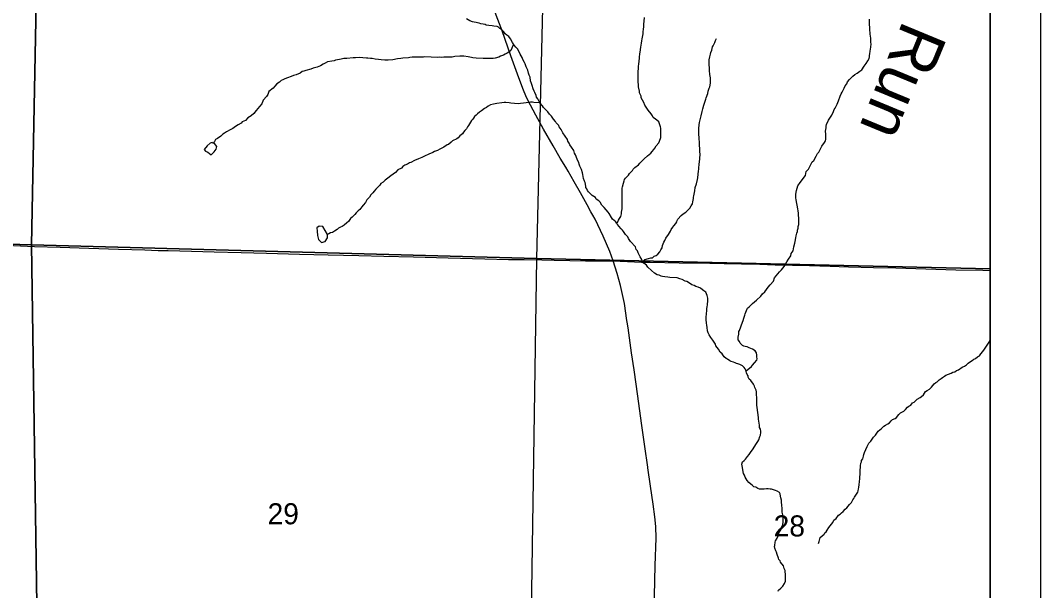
# Model space of a CAD drawing. Extents: x 0 to 34, y 0 to 22.
# Drawn here: x 6.971 to 9, y 18.998 to 20.132 of the extents above; entities that cross this region are included whole.
import ezdxf

# ---------------------------------------------------------------- set-up
doc = ezdxf.new("R2010")
doc.units = 0
for name, color, linetype in [('Default', 7, 'Continuous'), ('GM_X_Minor_River', 7, 'Continuous'), ('GM_X_Minor_River_Text', 7, 'Continuous'), ('GM_X_Section', 7, 'Continuous'), ('GM_X_Section_Text', 7, 'Continuous'), ('GM_X_State_Route', 7, 'Continuous'), ('SH_Data', 7, 'Continuous')]:
    doc.layers.add(name, color=color, linetype=linetype)

msp = doc.modelspace()

# ---------------------------------------------------------------- linework, layer by layer
at = {"layer": 'Default'}
for points in [[(8.9, 17.6104), (8.9, 20.9), (6.0871, 20.9), (6.0839, 20.7194), (6.0809, 20.5156), (6.08, 20.4768), (6.0777, 20.3704), (6.0696, 20.0002), (6.0632, 19.7108), (6.0568, 19.5343), (5.9893, 17.6676), (6.9889, 17.643), (7.0308, 17.6406), (8.0065, 17.6245)], [(8.9, 19.6382), (8.9, 20.6903), (8.0224, 20.7109), (7.9969, 19.6588)], [(8.9, 18.6218), (8.9, 19.6382), (7.9969, 19.6588), (7.9821, 18.6451)]]:
    msp.add_lwpolyline(points, close=True, dxfattribs=at)
at = {"layer": 'GM_X_Minor_River'}
for points in [[(7.9702, 20.0545), (7.9685, 20.0587), (7.9649, 20.0653), (7.9603, 20.0754), (7.9562, 20.0793), (7.9529, 20.0833), (7.9496, 20.0883), (7.9453, 20.0957), (7.9424, 20.1004), (7.9383, 20.1028), (7.9346, 20.106), (7.932, 20.1095), (7.928, 20.1135), (7.9242, 20.1163), (7.9213, 20.119), (7.9187, 20.1203), (7.9126, 20.1212), (7.9088, 20.1214), (7.9023, 20.122), (7.8974, 20.1233), (7.8948, 20.1241), (7.891, 20.125), (7.8868, 20.1259), (7.8834, 20.1268), (7.8796, 20.1277), (7.877, 20.1282), (7.8732, 20.1291), (7.8698, 20.1299), (7.8645, 20.1317), (7.8577, 20.1353)], [(8.1566, 19.7284), (8.1581, 19.7303), (8.1606, 19.7348), (8.1622, 19.7381), (8.1647, 19.7426), (8.1664, 19.7479), (8.1665, 19.7509), (8.1674, 19.7574), (8.1678, 19.7684), (8.1676, 19.7749), (8.1674, 19.778), (8.1675, 19.7821), (8.1673, 19.7871), (8.1677, 19.7989), (8.1681, 19.8015), (8.1703, 19.8087), (8.1716, 19.8132), (8.1724, 19.8159), (8.1744, 19.8185), (8.18, 19.8244), (8.1824, 19.8281), (8.1883, 19.8336), (8.1895, 19.8362), (8.1931, 19.8399), (8.2001, 19.8454), (8.2029, 19.8487), (8.208, 19.8535), (8.2116, 19.8572), (8.2183, 19.8631), (8.2246, 19.8686), (8.227, 19.8719), (8.2309, 19.8756), (8.2329, 19.8786), (8.2353, 19.8831), (8.2405, 19.8886), (8.2421, 19.8923), (8.2443, 19.8995), (8.2444, 19.9022), (8.2448, 19.9052), (8.2448, 19.9147), (8.2445, 19.9182), (8.2442, 19.9208), (8.2421, 19.927), (8.2404, 19.9305), (8.2363, 19.9337), (8.2337, 19.9361), (8.2296, 19.9393), (8.2278, 19.9424), (8.2252, 19.9463), (8.2194, 19.9541), (8.2169, 19.958), (8.2125, 19.9638), (8.2104, 19.9689), (8.2057, 19.9786), (8.2051, 19.9816), (8.2022, 19.9882), (8.202, 19.9916), (8.2003, 20.0005), (8.1998, 20.0054), (8.1995, 20.0089), (8.1994, 20.0165), (8.1996, 20.0249), (8.1994, 20.0291), (8.2001, 20.0386), (8.2002, 20.042), (8.2007, 20.045), (8.2013, 20.0519), (8.2018, 20.0564), (8.2019, 20.0591), (8.2029, 20.0659), (8.2034, 20.0693), (8.2045, 20.0792), (8.2063, 20.0875), (8.2068, 20.0921), (8.2077, 20.0958), (8.2082, 20.0989), (8.2092, 20.1057), (8.2094, 20.1103), (8.2099, 20.1144), (8.2105, 20.1205), (8.211, 20.1247), (8.2116, 20.1311), (8.2118, 20.1384)], [(8.5845, 19.9442), (8.5878, 19.9513), (8.5894, 19.9551), (8.5914, 19.9577), (8.5927, 19.9607), (8.5955, 19.9655), (8.5967, 19.9689), (8.598, 19.9727), (8.601, 19.9817), (8.6031, 19.9866), (8.6054, 19.9896), (8.6091, 19.9974), (8.6112, 20.0023), (8.6144, 20.0064), (8.6157, 20.0102), (8.62, 20.0146), (8.6267, 20.0212), (8.6307, 20.0249), (8.6353, 20.0274), (8.6404, 20.0318), (8.6443, 20.0343), (8.6491, 20.0414), (8.6507, 20.044), (8.6527, 20.0466), (8.6563, 20.0518), (8.6592, 20.057), (8.6597, 20.0601), (8.6598, 20.0627), (8.6602, 20.0658), (8.6608, 20.0715), (8.6626, 20.079), (8.6628, 20.0859), (8.6625, 20.0886), (8.6624, 20.0969), (8.6612, 20.1054), (8.6609, 20.1092), (8.6606, 20.1119), (8.6601, 20.1199), (8.6599, 20.1233), (8.6598, 20.1321), (8.6595, 20.1351)], [(8.2082, 19.6528), (8.2125, 19.6571), (8.2198, 19.6588), (8.2248, 19.6598), (8.2279, 19.6604), (8.231, 19.6634), (8.2353, 19.6647), (8.2384, 19.6673), (8.2424, 19.6717), (8.2448, 19.6758), (8.2469, 19.6803), (8.2478, 19.6849), (8.249, 19.6879), (8.2503, 19.6913), (8.2527, 19.6946), (8.2547, 19.6991), (8.2599, 19.7062), (8.2616, 19.7099), (8.2636, 19.7133), (8.2649, 19.7163), (8.2681, 19.7211), (8.2701, 19.7237), (8.2744, 19.7285), (8.2764, 19.7315), (8.2773, 19.7342), (8.2781, 19.7372), (8.2853, 19.7446), (8.2888, 19.7479), (8.2942, 19.7511), (8.297, 19.7537), (8.3021, 19.7588), (8.3046, 19.7633), (8.3074, 19.7678), (8.3079, 19.7716), (8.3093, 19.778), (8.3097, 19.7807), (8.3102, 19.7837), (8.3121, 19.7932), (8.313, 19.8), (8.3152, 19.8075), (8.3174, 19.8158), (8.3179, 19.8193), (8.3195, 19.8329), (8.32, 19.8356), (8.32, 19.8382), (8.3211, 19.8462), (8.3212, 19.8511), (8.3222, 19.8568), (8.3225, 19.8667), (8.3222, 19.8702), (8.3224, 19.8747), (8.3213, 19.8862), (8.3213, 19.8889), (8.3205, 19.8984), (8.32, 19.9068), (8.3202, 19.9106), (8.3199, 19.9137), (8.32, 19.9171), (8.3206, 19.9247), (8.3216, 19.9292), (8.3233, 19.9372), (8.3242, 19.9398), (8.3247, 19.9428), (8.3269, 19.9511), (8.3273, 19.9538), (8.3282, 19.9568), (8.3303, 19.9636), (8.3312, 19.9678), (8.3338, 19.9757), (8.3346, 19.9787), (8.338, 19.987), (8.3389, 19.9915), (8.341, 19.9975), (8.3419, 20.0005), (8.3427, 20.0039), (8.3433, 20.0081), (8.3435, 20.0142), (8.3432, 20.0184), (8.3426, 20.0215), (8.3423, 20.0249), (8.3414, 20.0326), (8.3412, 20.0371), (8.3407, 20.0455), (8.341, 20.0539), (8.3423, 20.06), (8.3433, 20.0656), (8.3437, 20.0683), (8.3462, 20.0735), (8.3476, 20.0796), (8.3488, 20.0822), (8.352, 20.0886), (8.3533, 20.0927), (8.355, 20.0965)], [(7.9514, 20.0855), (7.9481, 20.077), (7.9461, 20.0728), (7.9425, 20.0692), (7.9386, 20.067), (7.9351, 20.0652), (7.9316, 20.063), (7.9254, 20.061), (7.922, 20.0596), (7.9147, 20.0575), (7.9112, 20.0569), (7.9047, 20.0564), (7.891, 20.0568), (7.8769, 20.0573), (7.8704, 20.0583), (7.8678, 20.0588), (7.8647, 20.0593), (7.8613, 20.0601), (7.8526, 20.0612), (7.8488, 20.0613), (7.845, 20.0611), (7.835, 20.0607), (7.8297, 20.0593), (7.8243, 20.0591), (7.8132, 20.0591), (7.8075, 20.0589), (7.8045, 20.059), (7.8006, 20.0588), (7.7751, 20.0597), (7.7721, 20.0594), (7.7686, 20.0595), (7.7602, 20.0594), (7.7568, 20.0592), (7.7541, 20.0592), (7.7499, 20.059), (7.7453, 20.0584), (7.7423, 20.0581), (7.7316, 20.0574), (7.7273, 20.0564), (7.7204, 20.0558), (7.7174, 20.0556), (7.7147, 20.0549), (7.7112, 20.0542), (7.7021, 20.0534), (7.6986, 20.0532), (7.6956, 20.0533), (7.688, 20.0539), (7.6827, 20.0548), (7.6766, 20.0554), (7.6705, 20.0564), (7.6667, 20.0569), (7.6618, 20.0575), (7.6591, 20.0576), (7.6515, 20.0582), (7.645, 20.0584), (7.637, 20.0579), (7.6328, 20.0581), (7.6202, 20.057), (7.6163, 20.0567), (7.6137, 20.0568), (7.6087, 20.0555), (7.6052, 20.0548), (7.5975, 20.0532), (7.5945, 20.0522), (7.5902, 20.0515), (7.5814, 20.0499), (7.5767, 20.0474), (7.5725, 20.0453), (7.5678, 20.042), (7.5639, 20.041), (7.5608, 20.0396), (7.5582, 20.0389), (7.5532, 20.0376), (7.5481, 20.0355), (7.5381, 20.0328), (7.5343, 20.0318), (7.5312, 20.0307), (7.5269, 20.0278), (7.5191, 20.0243), (7.5137, 20.0226), (7.5091, 20.0208), (7.5018, 20.0184), (7.4964, 20.0163), (7.4925, 20.0145), (7.489, 20.0127), (7.4862, 20.0098), (7.4808, 20.0062), (7.4768, 20.0017), (7.4736, 19.9976), (7.465, 19.9907), (7.4625, 19.9851), (7.4601, 19.9813), (7.4534, 19.9736), (7.4505, 19.9664), (7.4461, 19.9609), (7.4429, 19.9572), (7.4397, 19.9531), (7.435, 19.9475), (7.4294, 19.9424), (7.4232, 19.9384), (7.4181, 19.9336)], [(8.2624, 19.6208), (8.2583, 19.6217), (8.2526, 19.6222), (8.248, 19.6228), (8.2453, 19.6233), (8.2409, 19.6257), (8.2374, 19.6266), (8.2322, 19.6294), (8.2263, 19.635), (8.2185, 19.6413), (8.2163, 19.6452), (8.2104, 19.6496), (8.2075, 19.6539), (8.2068, 19.657), (8.2032, 19.662), (8.1996, 19.6698), (8.1978, 19.674), (8.1956, 19.6768), (8.1939, 19.6818), (8.184, 19.6928), (8.1803, 19.6983), (8.1789, 19.7017), (8.1741, 19.7065), (8.1701, 19.7127), (8.1683, 19.7154), (8.1657, 19.7178), (8.161, 19.7233), (8.1591, 19.726), (8.1566, 19.7284), (8.1548, 19.7319), (8.1485, 19.7371), (8.1466, 19.7402), (8.1419, 19.748), (8.1401, 19.7507), (8.1361, 19.7558), (8.1317, 19.7605), (8.1273, 19.7649), (8.1236, 19.7707), (8.1211, 19.7734), (8.1162, 19.777), (8.1148, 19.7801), (8.1081, 19.7842), (8.104, 19.7878), (8.1007, 19.7913), (8.0985, 19.794), (8.0971, 19.7971), (8.0956, 19.7999), (8.0953, 19.8029), (8.0937, 19.8098), (8.0926, 19.8129), (8.0909, 19.8179), (8.0892, 19.826), (8.0886, 19.8294), (8.0869, 19.836), (8.0837, 19.8426), (8.0819, 19.8464), (8.0816, 19.8495), (8.0791, 19.8541), (8.0763, 19.8619), (8.0749, 19.8653), (8.0727, 19.8685), (8.0718, 19.8734), (8.067, 19.8801), (8.0634, 19.8848), (8.062, 19.8883), (8.0598, 19.8921), (8.0588, 19.8956), (8.0544, 19.9019), (8.0493, 19.9085), (8.0464, 19.9151), (8.0421, 19.9206), (8.0414, 19.9236), (8.0362, 19.9284), (8.0348, 19.9311), (8.0307, 19.9358), (8.0271, 19.9417), (8.0231, 19.946), (8.0198, 19.9503), (8.0165, 19.9538), (8.0113, 19.959), (8.0091, 19.9625), (8.0047, 19.9679), (8.0022, 19.9711), (7.9997, 19.9761), (7.9975, 19.98), (7.9968, 19.9831), (7.994, 19.9893), (7.9926, 19.992), (7.9908, 19.9966), (7.9884, 20.0032), (7.987, 20.0067), (7.9856, 20.0124), (7.9843, 20.0197), (7.9829, 20.0232), (7.9815, 20.0274), (7.9798, 20.0332), (7.9788, 20.0363), (7.9766, 20.0402), (7.9745, 20.0463), (7.9735, 20.049), (7.9702, 20.0545)], [(8.0043, 19.9685), (7.9922, 19.9691), (7.9891, 19.9696), (7.9853, 19.9698), (7.9811, 19.9691), (7.9765, 19.9685), (7.9712, 19.968), (7.9654, 19.967), (7.9616, 19.9668), (7.9532, 19.9671), (7.946, 19.9677), (7.943, 19.9685), (7.9365, 19.9692), (7.9327, 19.9689), (7.9285, 19.9687), (7.9185, 19.9671), (7.915, 19.9665), (7.912, 19.9658), (7.9054, 19.9645), (7.9008, 19.9616), (7.8976, 19.9591), (7.8937, 19.9569), (7.8875, 19.9526), (7.884, 19.9496), (7.8797, 19.9467), (7.8769, 19.9438), (7.8742, 19.9412), (7.8721, 19.9382), (7.8698, 19.9356), (7.8678, 19.933), (7.8617, 19.9237), (7.8597, 19.9204), (7.8577, 19.9166), (7.8549, 19.9137), (7.8521, 19.91), (7.8501, 19.9066), (7.845, 19.9026), (7.8411, 19.8989), (7.8384, 19.8971), (7.8302, 19.8928), (7.8274, 19.8899), (7.822, 19.8858), (7.8193, 19.8852), (7.8126, 19.8805), (7.8052, 19.8765), (7.8006, 19.8736), (7.794, 19.8716), (7.7909, 19.8698), (7.7828, 19.8666), (7.7743, 19.8623), (7.7715, 19.8613), (7.7688, 19.8599), (7.7626, 19.857), (7.7545, 19.8539), (7.7475, 19.8495), (7.7448, 19.8489), (7.7405, 19.8464), (7.7355, 19.8446), (7.7316, 19.8421), (7.7284, 19.8384), (7.7215, 19.8352), (7.7167, 19.83), (7.712, 19.8268), (7.7073, 19.8231), (7.7018, 19.8184), (7.696, 19.8147), (7.6924, 19.8107), (7.6878, 19.8078), (7.6854, 19.8048), (7.6814, 19.8008), (7.6778, 19.7967), (7.6743, 19.793), (7.6715, 19.7897), (7.6679, 19.7852), (7.6647, 19.7808), (7.66, 19.7752), (7.6568, 19.7704), (7.6524, 19.7652), (7.65, 19.7615), (7.646, 19.7563), (7.6425, 19.7537), (7.6385, 19.7493), (7.6361, 19.7463), (7.6302, 19.7408), (7.6271, 19.7386), (7.6231, 19.7327), (7.6199, 19.7294), (7.6148, 19.7253), (7.6105, 19.7224), (7.607, 19.721), (7.6036, 19.7192), (7.6008, 19.7163), (7.5957, 19.7134), (7.5914, 19.7105), (7.5876, 19.7095), (7.5841, 19.7081), (7.5814, 19.7067)], [(7.4181, 19.9336), (7.4119, 19.9308), (7.4095, 19.9282), (7.4037, 19.925), (7.3986, 19.9217), (7.3928, 19.9177), (7.3881, 19.9145), (7.3803, 19.9106), (7.3768, 19.9084), (7.3733, 19.9058), (7.3694, 19.9022), (7.3623, 19.8978), (7.3585, 19.8957), (7.3565, 19.8917)], [(8.4141, 19.4352), (8.4251, 19.4441), (8.4271, 19.4467), (8.4307, 19.4515), (8.4355, 19.4567), (8.4359, 19.4593), (8.4357, 19.4632), (8.4354, 19.4666), (8.4348, 19.4708), (8.4323, 19.4751), (8.427, 19.4787), (8.4203, 19.4812), (8.4161, 19.4829), (8.4123, 19.4838), (8.4097, 19.4842), (8.4067, 19.4855), (8.4023, 19.4906), (8.4008, 19.4937), (8.3987, 19.4972), (8.3985, 19.5025), (8.3994, 19.5082), (8.4, 19.5132), (8.4012, 19.5158), (8.4037, 19.5225), (8.405, 19.5267), (8.4083, 19.5353), (8.4096, 19.5399), (8.4117, 19.5459), (8.4122, 19.5485), (8.4151, 19.5553), (8.4172, 19.5598), (8.4203, 19.5627), (8.427, 19.5694), (8.4306, 19.5727), (8.4349, 19.576), (8.4435, 19.584), (8.4471, 19.5885), (8.4514, 19.5922), (8.4579, 19.6018), (8.4618, 19.6067), (8.4689, 19.614), (8.4707, 19.6204), (8.4806, 19.6323), (8.4846, 19.6364), (8.4901, 19.6426), (8.4954, 19.6524), (8.4982, 19.6572), (8.503, 19.6639), (8.504, 19.6688), (8.5079, 19.674), (8.509, 19.682), (8.5111, 19.6895), (8.5116, 19.6929), (8.513, 19.7001), (8.5139, 19.7039), (8.5148, 19.7092), (8.5161, 19.7122), (8.5162, 19.7149), (8.5175, 19.719), (8.5179, 19.7224), (8.5188, 19.7262), (8.5193, 19.7289), (8.5192, 19.7365), (8.5189, 19.7396), (8.5183, 19.7442), (8.5184, 19.748), (8.5175, 19.7541), (8.5172, 19.7568), (8.5162, 19.7618), (8.5146, 19.7713), (8.5136, 19.7759), (8.513, 19.7786), (8.5128, 19.7843), (8.5129, 19.787), (8.5146, 19.7942), (8.5172, 19.8036), (8.522, 19.8099), (8.532, 19.8237), (8.5334, 19.8316), (8.5382, 19.8364), (8.5439, 19.8473), (8.5459, 19.8514), (8.5487, 19.854), (8.5535, 19.8622), (8.556, 19.8674), (8.5587, 19.8704), (8.5628, 19.8783), (8.5649, 19.8824), (8.5701, 19.8898), (8.5721, 19.8928), (8.5729, 19.8958), (8.5731, 19.8992), (8.5725, 19.9061), (8.5723, 19.9118), (8.5725, 19.9156), (8.5733, 19.919), (8.5734, 19.9221), (8.5743, 19.9251), (8.578, 19.9341), (8.5805, 19.9382), (8.5845, 19.9442)], [(7.3521, 19.8898), (7.348, 19.8885), (7.3422, 19.8829), (7.3359, 19.8759), (7.3388, 19.8724), (7.3437, 19.87), (7.35, 19.8649), (7.3563, 19.8712), (7.3602, 19.8764), (7.3611, 19.8813), (7.3567, 19.8878)], [(7.352, 19.8898), (7.3567, 19.8878)], [(7.3565, 19.8917), (7.3549, 19.8886)], [(7.5814, 19.7067), (7.5724, 19.7225), (7.5648, 19.7231), (7.5601, 19.7201), (7.5607, 19.7129), (7.5616, 19.7042), (7.5637, 19.6965), (7.5696, 19.6907), (7.5765, 19.6927), (7.5812, 19.7002)], [(7.5812, 19.7002), (7.5817, 19.7047), (7.5814, 19.7067)], [(8.3708, 19.4631), (8.3668, 19.4693), (8.3628, 19.4725), (8.3595, 19.4787), (8.3566, 19.4815), (8.354, 19.485), (8.3534, 19.4881), (8.3483, 19.4966), (8.3443, 19.5014), (8.3406, 19.5072), (8.3389, 19.5111), (8.3375, 19.5149), (8.3366, 19.5218), (8.3363, 19.526), (8.3357, 19.5298), (8.3348, 19.5371), (8.3349, 19.5402), (8.335, 19.5428), (8.3355, 19.5481), (8.3362, 19.5557), (8.3363, 19.5588), (8.3368, 19.5633), (8.3373, 19.566), (8.3374, 19.569), (8.3379, 19.5728), (8.3381, 19.5797), (8.3368, 19.5854), (8.3339, 19.5916), (8.3302, 19.5944), (8.3276, 19.5964), (8.3235, 19.5996), (8.3186, 19.6017), (8.3145, 19.6033), (8.3107, 19.605), (8.3062, 19.6067), (8.3013, 19.6095), (8.2961, 19.6127), (8.2927, 19.614), (8.2867, 19.6169), (8.2822, 19.6182), (8.2769, 19.6203), (8.2624, 19.6208)], [(8.8814, 19.4692), (8.8853, 19.4736), (8.8882, 19.4781), (8.891, 19.4822), (8.8938, 19.4866), (8.8966, 19.4903), (8.9, 19.4953)], [(8.4724, 19.0968), (8.4759, 19.1021), (8.4779, 19.107), (8.4784, 19.11), (8.4801, 19.1142), (8.4825, 19.1179), (8.4842, 19.122), (8.4858, 19.1254), (8.4875, 19.1295), (8.4876, 19.1341), (8.4881, 19.1367), (8.4876, 19.1451), (8.4873, 19.1486), (8.486, 19.154), (8.4861, 19.1574), (8.4859, 19.1627), (8.4853, 19.1666), (8.4848, 19.175), (8.4845, 19.178), (8.4835, 19.1826), (8.4829, 19.1861), (8.4819, 19.1907), (8.4804, 19.1934), (8.476, 19.1958), (8.4729, 19.1971), (8.465, 19.1996), (8.462, 19.1997), (8.4582, 19.2003), (8.4547, 19.2004), (8.4501, 19.1998), (8.4406, 19.2001), (8.4372, 19.201), (8.4335, 19.2038), (8.4297, 19.2047), (8.426, 19.2075), (8.4234, 19.2098), (8.4193, 19.213), (8.416, 19.2173), (8.4124, 19.2239), (8.411, 19.2278), (8.4092, 19.2309), (8.4076, 19.2382), (8.407, 19.2432), (8.4057, 19.2497), (8.407, 19.2542), (8.4101, 19.2572), (8.4128, 19.2593), (8.4168, 19.2649), (8.4204, 19.2686), (8.424, 19.275), (8.4268, 19.2779), (8.4313, 19.2854), (8.4333, 19.2887), (8.4377, 19.2947), (8.4393, 19.2977), (8.4414, 19.3048), (8.4427, 19.3075), (8.4436, 19.3124), (8.4433, 19.3151), (8.4427, 19.3193), (8.4409, 19.3228), (8.4407, 19.3274), (8.4388, 19.3388), (8.4385, 19.3423), (8.4373, 19.3522), (8.4367, 19.3568), (8.4361, 19.3629), (8.4355, 19.366), (8.4356, 19.3687), (8.4355, 19.3774), (8.4356, 19.3816), (8.4351, 19.3881), (8.4348, 19.3912), (8.4349, 19.3938), (8.4342, 19.3965), (8.4313, 19.402), (8.4311, 19.4046), (8.4289, 19.4085), (8.4234, 19.416), (8.4205, 19.4187), (8.4183, 19.4226), (8.418, 19.4253), (8.4162, 19.428), (8.4151, 19.4311), (8.4145, 19.4338), (8.4138, 19.4365), (8.4124, 19.4392), (8.4106, 19.4419), (8.4072, 19.4455), (8.4042, 19.4467), (8.4016, 19.4476), (8.3974, 19.4492), (8.3948, 19.4497), (8.3922, 19.4509), (8.3888, 19.4526), (8.3843, 19.4539), (8.3816, 19.4555), (8.3772, 19.4583), (8.3745, 19.4599), (8.3708, 19.4631)], [(8.5579, 19.0917), (8.5592, 19.0958), (8.5617, 19.1037), (8.5696, 19.1103), (8.5708, 19.1129), (8.5736, 19.1151), (8.5756, 19.1181), (8.5788, 19.1237), (8.5868, 19.1333), (8.5884, 19.1379), (8.5935, 19.1415), (8.5979, 19.1478), (8.6011, 19.15), (8.6038, 19.153), (8.607, 19.1555), (8.6113, 19.1599), (8.6148, 19.1625), (8.62, 19.1695), (8.6236, 19.1732), (8.6264, 19.1785), (8.6284, 19.1811), (8.63, 19.1837), (8.6337, 19.19), (8.6365, 19.1941), (8.6369, 19.1968), (8.6378, 19.2005), (8.6387, 19.2032), (8.6389, 19.2093), (8.6398, 19.2142), (8.6401, 19.2214), (8.6406, 19.2252), (8.6411, 19.2286), (8.6408, 19.2328), (8.6414, 19.2389), (8.6415, 19.2423), (8.642, 19.2465), (8.6426, 19.2514), (8.6438, 19.2544), (8.6439, 19.2571), (8.6463, 19.2601), (8.6476, 19.2654), (8.6485, 19.2688), (8.6498, 19.2729), (8.6551, 19.2849), (8.658, 19.2913), (8.662, 19.2953), (8.6676, 19.3032), (8.6715, 19.3072), (8.6767, 19.315), (8.6803, 19.318), (8.683, 19.3198), (8.6882, 19.3253), (8.6913, 19.3275), (8.6963, 19.3296), (8.6994, 19.3318), (8.7026, 19.3359), (8.7054, 19.3384), (8.7104, 19.3402), (8.7135, 19.3427), (8.7183, 19.3483), (8.7211, 19.352), (8.7277, 19.3552), (8.7312, 19.3581), (8.7352, 19.3633), (8.7379, 19.3651), (8.7418, 19.3673), (8.7454, 19.3717), (8.7485, 19.3731), (8.7544, 19.3787), (8.7602, 19.3823), (8.763, 19.3841), (8.7673, 19.3877), (8.7713, 19.3941), (8.7744, 19.3963), (8.7787, 19.3988), (8.7827, 19.4028), (8.7882, 19.4091), (8.7914, 19.4121), (8.7945, 19.4135), (8.7984, 19.4171), (8.8023, 19.4197), (8.805, 19.4219), (8.8086, 19.4244), (8.8117, 19.4266), (8.8167, 19.4287), (8.8221, 19.4308), (8.8252, 19.4326), (8.8295, 19.4336), (8.8326, 19.4358), (8.8368, 19.4372), (8.8443, 19.4426), (8.8489, 19.4447), (8.8528, 19.4473), (8.8556, 19.4506), (8.8587, 19.4524), (8.8642, 19.456), (8.8673, 19.4586), (8.8704, 19.46), (8.8747, 19.4629), (8.8782, 19.4654), (8.8814, 19.4692)], [(8.4789, 18.9991), (8.4831, 19.0028), (8.487, 19.0068), (8.4906, 19.0121), (8.4926, 19.0166), (8.4927, 19.0242), (8.4925, 19.0306), (8.4922, 19.0356), (8.4919, 19.0382), (8.4901, 19.0421), (8.4894, 19.0444), (8.4883, 19.0475), (8.4828, 19.0544), (8.4817, 19.0571), (8.4795, 19.0598), (8.4788, 19.0625), (8.4759, 19.0698), (8.4749, 19.0744), (8.4734, 19.0771), (8.4713, 19.0828), (8.4706, 19.0855), (8.4714, 19.0881), (8.4719, 19.0946), (8.4724, 19.0968)], [(8.4777, 18.9968), (8.4789, 18.9991)]]:
    msp.add_lwpolyline(points, dxfattribs=at)
at = {"layer": 'GM_X_Section'}
for points in [[(6.0815, 20.7216), (7.0125, 20.7168), (6.9929, 19.6861), (6.0653, 19.7127)], [(7.0125, 20.7168), (8.0224, 20.7109), (7.9969, 19.6588), (6.9929, 19.6861)], [(6.9929, 19.6861), (7.008, 18.6577), (6.0336, 18.6715), (6.0653, 19.7127)], [(6.9929, 19.6861), (7.9969, 19.6588), (7.9821, 18.6451), (7.008, 18.6577)]]:
    msp.add_lwpolyline(points, close=True, dxfattribs=at)
at = {"layer": 'GM_X_State_Route'}
for points in [[(8.0553, 19.8403), (8.0445, 19.8583), (8.0302, 19.8831), (8.0114, 19.9164), (7.9958, 19.9437), (7.985, 19.9641), (7.9775, 19.9794), (7.9702, 19.997), (7.9595, 20.0255), (7.9462, 20.0622), (7.9288, 20.1115), (7.9149, 20.1482)], [(8.109, 19.7452), (8.1051, 19.7519), (8.098, 19.7657), (8.085, 19.7895), (8.0721, 19.8111), (8.0599, 19.8326), (8.0553, 19.8403)], [(8.1771, 19.5354), (8.1721, 19.569), (8.1643, 19.605), (8.158, 19.6286), (8.1498, 19.6543), (8.1432, 19.673), (8.13, 19.7035), (8.1139, 19.7368), (8.109, 19.7452)], [(6.9429, 19.6851), (6.9988, 19.6828), (7.0494, 19.6813), (7.1068, 19.6794), (7.166, 19.6776), (7.2184, 19.6757), (7.2443, 19.6749), (7.2643, 19.6745), (7.3112, 19.6735), (7.3561, 19.6722), (7.4099, 19.6707), (7.4604, 19.6695), (7.5258, 19.6674), (7.5831, 19.6659), (7.6437, 19.6648), (7.6937, 19.6636), (7.7527, 19.662), (7.8215, 19.66), (7.8946, 19.6581), (7.9417, 19.6571), (7.9587, 19.657)], [(7.9587, 19.657), (7.9727, 19.6569), (8.0075, 19.6558), (8.0325, 19.6557), (8.0945, 19.6543), (8.1498, 19.6543), (8.2064, 19.6518), (8.2233, 19.6515), (8.2813, 19.6504), (8.3417, 19.6493), (8.3705, 19.6488)], [(8.3705, 19.6488), (8.4051, 19.6482), (8.4414, 19.6474), (8.4719, 19.6464), (8.5402, 19.6448), (8.5606, 19.6444)], [(8.5606, 19.6444), (8.5626, 19.6443), (8.6178, 19.6423), (8.6673, 19.6411), (8.7123, 19.6402), (8.7717, 19.6385), (8.8312, 19.6365), (8.8853, 19.6356), (8.9, 19.6352)], [(8.2189, 19.2423), (8.2188, 19.2433), (8.213, 19.2846), (8.206, 19.3309), (8.1988, 19.3851), (8.1914, 19.4371), (8.1864, 19.4713), (8.1794, 19.5207), (8.1776, 19.5324), (8.1771, 19.5354)], [(8.232, 18.9775), (8.2322, 18.9878), (8.2332, 19.0483), (8.2351, 19.1022), (8.2345, 19.1255), (8.2326, 19.1447), (8.2293, 19.1698), (8.2242, 19.2057), (8.2189, 19.2423)]]:
    msp.add_lwpolyline(points, dxfattribs=at)
at = {"layer": 'SH_Data'}
for p, q in [((9, 21), (9, 14)), ((8.9, 20.9), (8.9, 14.1))]:
    msp.add_line(p, q, dxfattribs=at)

# ---------------------------------------------------------------- texts
at = {"layer": 'GM_X_Minor_River_Text'}
msp.add_text('Run', height=0.09467, rotation=247.5027, dxfattribs=at).set_placement((8.7275, 20.1351))
at = {"layer": 'GM_X_Section_Text'}
for s, p in [('29', (7.4623, 19.13)), ('28', (8.469, 19.1058))]:
    msp.add_text(s, height=0.04186, rotation=0, dxfattribs=at).set_placement(p)

doc.saveas('drawing.dxf')
